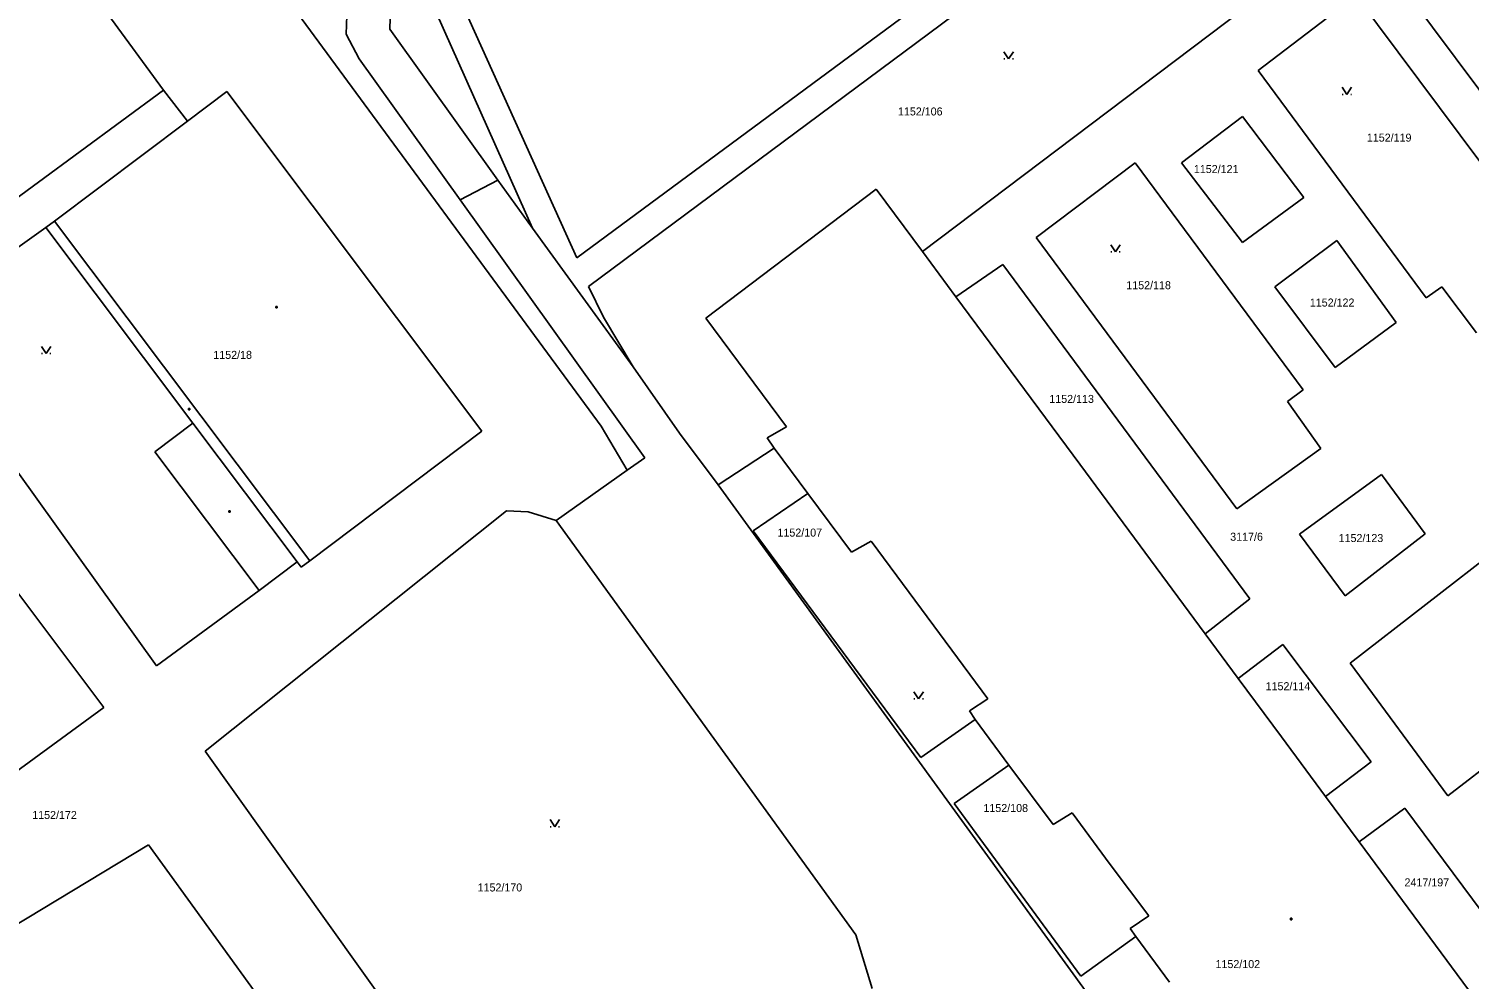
# Model space of a CAD drawing. Extents: x -609709 to -609357, y -1051535 to -1051131.
# Drawn here: x -609619.2 to -609542.7, y -1051439.1 to -1051388.6 of the extents above; entities that cross this region are included whole.
import ezdxf

# ---------------------------------------------------------------- set-up
doc = ezdxf.new("R2010")
doc.units = 0
doc.layers.add('Vrstva 10', color=7, linetype='Continuous')

msp = doc.modelspace()

# ---------------------------------------------------------------- linework, layer by layer
at = {"layer": 'Vrstva 10'}
for p, q in [((-609602.32, -1051388.88), (-609601.74, -1051372.86)), ((-609600, -1051388.61), (-609599.55, -1051372.92)), ((-609590.06, -1051400.76), (-609556.61, -1051376.01)), ((-609589.45, -1051402.27), (-609555.75, -1051377.2)), ((-609571.71, -1051400.42), (-609550.46, -1051384.37)), ((-609598.65, -1051385.24), (-609592.42, -1051399.18)), ((-609597.16, -1051385.07), (-609590.06, -1051400.76)), ((-609546.85, -1051385.48), (-609539.99, -1051394.71)), ((-609606.02, -1051386.23), (-609588.77, -1051409.69)), ((-609553.88, -1051390.81), (-609548.67, -1051386.83)), ((-609548.67, -1051386.83), (-609537.77, -1051401.44)), ((-609614.98, -1051387.81), (-609612.03, -1051391.85)), ((-609602.32, -1051388.88), (-609601.63, -1051390.19)), ((-609600, -1051388.61), (-609594.26, -1051396.62)), ((-609567.38, -1051389.805), (-609567.13, -1051390.18)), ((-609567.13, -1051390.18), (-609566.88, -1051389.805)), ((-609601.63, -1051390.19), (-609596.26, -1051397.68)), ((-609567.38, -1051390.18), (-609567.33, -1051390.18)), ((-609566.93, -1051390.18), (-609566.88, -1051390.18)), ((-609553.88, -1051390.81), (-609544.95, -1051402.88)), ((-609621.66, -1051398.92), (-609612.03, -1051391.85)), ((-609612.03, -1051391.85), (-609610.76, -1051393.49)), ((-609610.76, -1051393.49), (-609608.67, -1051391.92)), ((-609608.67, -1051391.92), (-609595.11, -1051409.96)), ((-609549.41, -1051391.695), (-609549.16, -1051392.07)), ((-609549.41, -1051392.07), (-609549.36, -1051392.07)), ((-609549.16, -1051392.07), (-609548.91, -1051391.695)), ((-609548.96, -1051392.07), (-609548.91, -1051392.07)), ((-609617.82, -1051398.8), (-609610.76, -1051393.49)), ((-609557.94, -1051395.7), (-609554.7, -1051393.25)), ((-609554.7, -1051393.25), (-609551.44, -1051397.55)), ((-609565.66, -1051399.68), (-609560.41, -1051395.71)), ((-609560.41, -1051395.71), (-609551.49, -1051407.77)), ((-609557.94, -1051395.7), (-609554.71, -1051399.94)), ((-609596.26, -1051397.68), (-609594.26, -1051396.62)), ((-609594.26, -1051396.62), (-609592.42, -1051399.18)), ((-609583.21, -1051403.95), (-609574.16, -1051397.11)), ((-609574.16, -1051397.11), (-609571.71, -1051400.42)), ((-609596.26, -1051397.68), (-609586.45, -1051411.38)), ((-609554.71, -1051399.94), (-609551.44, -1051397.55)), ((-609618.27, -1051399.14), (-609617.82, -1051398.8)), ((-609617.82, -1051398.8), (-609604.26, -1051416.84)), ((-609626.11, -1051404.7), (-609618.27, -1051399.14)), ((-609618.27, -1051399.14), (-609610.47, -1051409.53)), ((-609592.42, -1051399.18), (-609587.07, -1051406.55)), ((-609565.66, -1051399.68), (-609555, -1051414.09)), ((-609571.71, -1051400.42), (-609569.93, -1051402.83)), ((-609561.7, -1051400.055), (-609561.45, -1051400.43)), ((-609561.7, -1051400.43), (-609561.65, -1051400.43)), ((-609561.45, -1051400.43), (-609561.2, -1051400.055)), ((-609561.25, -1051400.43), (-609561.2, -1051400.43)), ((-609552.99, -1051402.29), (-609549.7, -1051399.84)), ((-609549.7, -1051399.84), (-609546.54, -1051404.18)), ((-609569.93, -1051402.83), (-609567.43, -1051401.11)), ((-609567.43, -1051401.11), (-609554.31, -1051418.87)), ((-609589.45, -1051402.27), (-609588.65, -1051403.9)), ((-609569.93, -1051402.83), (-609563.35, -1051411.72)), ((-609552.99, -1051402.29), (-609549.78, -1051406.58)), ((-609544.95, -1051402.88), (-609544.12, -1051402.29)), ((-609544.12, -1051402.29), (-609542.27, -1051404.73)), ((-609606.065, -1051403.335), (-609605.99, -1051403.335)), ((-609606.065, -1051403.41), (-609606.065, -1051403.335)), ((-609605.99, -1051403.41), (-609606.065, -1051403.41)), ((-609605.99, -1051403.335), (-609605.99, -1051403.41)), ((-609588.65, -1051403.9), (-609587.07, -1051406.55)), ((-609583.21, -1051403.95), (-609578.93, -1051409.73)), ((-609549.78, -1051406.58), (-609546.54, -1051404.18)), ((-609618.51, -1051405.465), (-609618.26, -1051405.84)), ((-609618.51, -1051405.84), (-609618.46, -1051405.84)), ((-609618.26, -1051405.84), (-609618.01, -1051405.465)), ((-609618.06, -1051405.84), (-609618.01, -1051405.84)), ((-609587.07, -1051406.55), (-609584.62, -1051410.06)), ((-609552.32, -1051408.38), (-609551.49, -1051407.77)), ((-609610.705, -1051408.755), (-609610.63, -1051408.755)), ((-609610.705, -1051408.83), (-609610.705, -1051408.755)), ((-609610.63, -1051408.83), (-609610.705, -1051408.83)), ((-609610.63, -1051408.755), (-609610.63, -1051408.83)), ((-609552.32, -1051408.38), (-609550.54, -1051410.88)), ((-609612.49, -1051411.05), (-609610.47, -1051409.53)), ((-609610.47, -1051409.53), (-609604.93, -1051416.9)), ((-609588.77, -1051409.69), (-609587.39, -1051412.04)), ((-609579.96, -1051410.31), (-609578.93, -1051409.73)), ((-609548.99, -1051422.29), (-609532.07, -1051409.15)), ((-609621.11, -1051410.27), (-609612.4, -1051422.42)), ((-609604.26, -1051416.84), (-609595.11, -1051409.96)), ((-609584.62, -1051410.06), (-609582.56, -1051412.81)), ((-609579.96, -1051410.31), (-609579.59, -1051410.86)), ((-609612.49, -1051411.05), (-609606.95, -1051418.42)), ((-609582.56, -1051412.81), (-609579.59, -1051410.86)), ((-609579.59, -1051410.86), (-609577.8, -1051413.27)), ((-609555, -1051414.09), (-609550.54, -1051410.88)), ((-609587.39, -1051412.04), (-609586.45, -1051411.38)), ((-609563.35, -1051411.72), (-609556.69, -1051420.73)), ((-609624.18, -1051412.69), (-609615.2, -1051424.63)), ((-609591.17, -1051414.7), (-609587.39, -1051412.04)), ((-609551.67, -1051415.44), (-609547.33, -1051412.26)), ((-609547.33, -1051412.26), (-609545, -1051415.41)), ((-609582.56, -1051412.81), (-609561.16, -1051442.27)), ((-609580.7, -1051415.25), (-609577.8, -1051413.27)), ((-609577.8, -1051413.27), (-609575.47, -1051416.38)), ((-609609.81, -1051426.95), (-609593.81, -1051414.2)), ((-609608.555, -1051414.195), (-609608.48, -1051414.195)), ((-609608.555, -1051414.27), (-609608.555, -1051414.195)), ((-609608.48, -1051414.27), (-609608.555, -1051414.27)), ((-609608.48, -1051414.195), (-609608.48, -1051414.27)), ((-609593.81, -1051414.2), (-609592.66, -1051414.24)), ((-609592.66, -1051414.24), (-609591.17, -1051414.7)), ((-609591.17, -1051414.7), (-609575.25, -1051436.72)), ((-609580.7, -1051415.25), (-609571.8, -1051427.3)), ((-609575.47, -1051416.38), (-609574.43, -1051415.8)), ((-609574.43, -1051415.8), (-609572.41, -1051418.53)), ((-609551.67, -1051415.44), (-609549.26, -1051418.7)), ((-609549.26, -1051418.7), (-609545, -1051415.41)), ((-609543.79, -1051429.33), (-609526.85, -1051416.16)), ((-609606.95, -1051418.42), (-609604.93, -1051416.9)), ((-609604.93, -1051416.9), (-609604.72, -1051417.18)), ((-609604.72, -1051417.18), (-609604.26, -1051416.84)), ((-609612.4, -1051422.42), (-609606.95, -1051418.42)), ((-609572.41, -1051418.53), (-609568.24, -1051424.17)), ((-609556.69, -1051420.73), (-609554.31, -1051418.87)), ((-609556.69, -1051420.73), (-609554.94, -1051423.09)), ((-609554.94, -1051423.09), (-609552.56, -1051421.29)), ((-609552.56, -1051421.29), (-609547.87, -1051427.53)), ((-609548.99, -1051422.29), (-609543.79, -1051429.33)), ((-609554.94, -1051423.09), (-609552.64, -1051426.2)), ((-609572.16, -1051423.805), (-609571.91, -1051424.18)), ((-609572.16, -1051424.18), (-609572.11, -1051424.18)), ((-609571.91, -1051424.18), (-609571.66, -1051423.805)), ((-609571.71, -1051424.18), (-609571.66, -1051424.18)), ((-609569.21, -1051424.82), (-609568.24, -1051424.17)), ((-609624.4, -1051431.37), (-609615.2, -1051424.63)), ((-609569.21, -1051424.82), (-609568.91, -1051425.28)), ((-609571.8, -1051427.3), (-609568.91, -1051425.28)), ((-609568.91, -1051425.28), (-609567.12, -1051427.7)), ((-609552.64, -1051426.2), (-609550.3, -1051429.37)), ((-609609.81, -1051426.95), (-609590.2, -1051454.46)), ((-609570.02, -1051429.73), (-609567.12, -1051427.7)), ((-609567.12, -1051427.7), (-609564.76, -1051430.85)), ((-609550.3, -1051429.37), (-609547.87, -1051427.53)), ((-609550.3, -1051429.37), (-609548.51, -1051431.78)), ((-609570.02, -1051429.73), (-609563.29, -1051438.91)), ((-609564.76, -1051430.85), (-609563.75, -1051430.24)), ((-609563.75, -1051430.24), (-609561.73, -1051432.97)), ((-609548.51, -1051431.78), (-609546.08, -1051429.98)), ((-609546.08, -1051429.98), (-609536.87, -1051442.41)), ((-609591.49, -1051430.595), (-609591.24, -1051430.97)), ((-609591.49, -1051430.97), (-609591.44, -1051430.97)), ((-609591.24, -1051430.97), (-609590.99, -1051430.595)), ((-609591.04, -1051430.97), (-609590.99, -1051430.97)), ((-609548.51, -1051431.78), (-609541.79, -1051440.87)), ((-609623.33, -1051438.28), (-609612.82, -1051431.94)), ((-609612.82, -1051431.94), (-609594.06, -1051457.83)), ((-609561.73, -1051432.97), (-609559.69, -1051435.71)), ((-609560.68, -1051436.37), (-609559.69, -1051435.71)), ((-609560.68, -1051436.37), (-609560.37, -1051436.81)), ((-609552.155, -1051435.835), (-609552.08, -1051435.835)), ((-609552.155, -1051435.91), (-609552.155, -1051435.835)), ((-609552.08, -1051435.91), (-609552.155, -1051435.91)), ((-609552.08, -1051435.835), (-609552.08, -1051435.91)), ((-609575.25, -1051436.72), (-609574.38, -1051439.57)), ((-609563.29, -1051438.91), (-609560.37, -1051436.81)), ((-609560.37, -1051436.81), (-609558.58, -1051439.23))]:
    msp.add_line(p, q, dxfattribs=at)

# ---------------------------------------------------------------- texts
for s, p in [('1152/106', (-609573.01, -1051393.19)), ('1152/119', (-609548.1, -1051394.58)), ('1152/121', (-609557.29, -1051396.25)), ('1152/118', (-609560.88, -1051402.42)), ('1152/122', (-609551.13, -1051403.34)), ('1152/18', (-609609.38, -1051406.12)), ('1152/113', (-609564.97, -1051408.46)), ('1152/107', (-609579.41, -1051415.56)), ('3117/6', (-609555.36, -1051415.78)), ('1152/123', (-609549.6, -1051415.85)), ('1152/114', (-609553.48, -1051423.72)), ('1152/172', (-609619, -1051430.56)), ('1152/108', (-609568.47, -1051430.19)), ('1152/170', (-609595.34, -1051434.41)), ('2417/197', (-609546.1, -1051434.14)), ('1152/102', (-609556.14, -1051438.48))]:
    msp.add_text(s, height=0.425, dxfattribs=at).set_placement(p)

doc.saveas('drawing.dxf')
